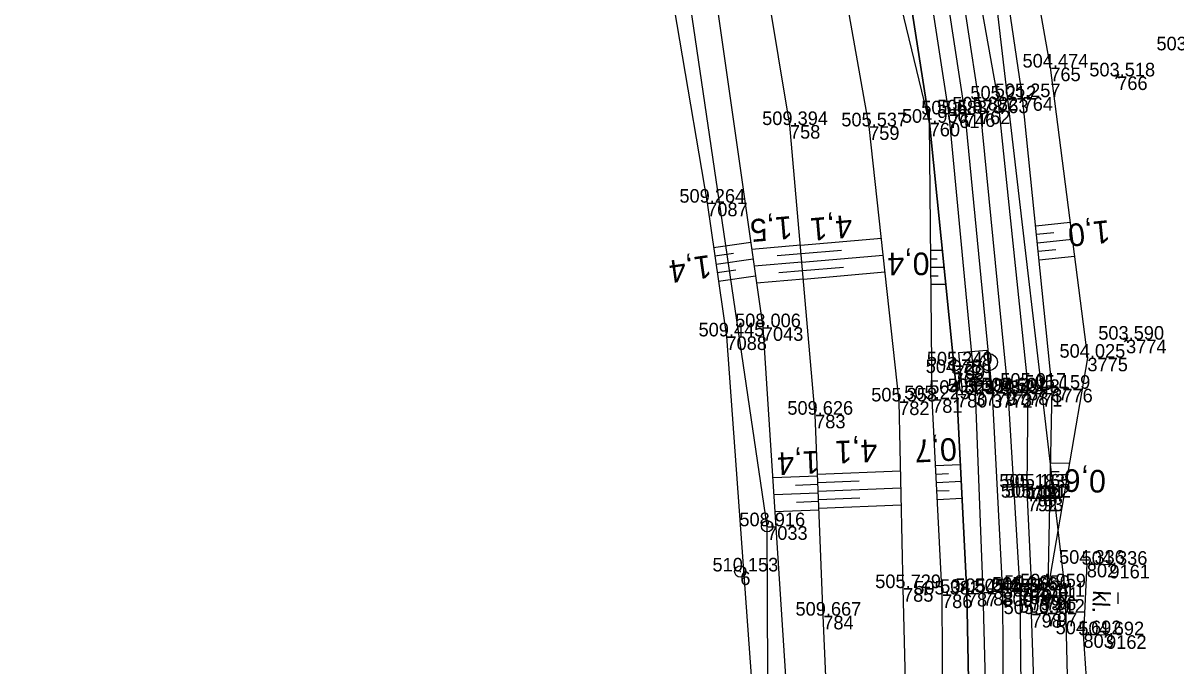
# Model space of a CAD drawing. Extents: x -1234191 to 23050, y -1290331 to -741191.
# Drawn here: x -865217.8 to -865116.1, y -1106225.5 to -1106168.8 of the extents above; entities that cross this region are included whole.
import ezdxf

# ---------------------------------------------------------------- set-up
doc = ezdxf.new("R2010")
doc.units = 0
for name, color, linetype in [('Vrstva 1', 7, 'Continuous'), ('Vrstva 12', 7, 'Continuous'), ('Vrstva 17', 7, 'Continuous'), ('Vrstva 23', 7, 'Continuous'), ('Vrstva 4', 7, 'Continuous'), ('Vrstva 48', 7, 'Continuous'), ('Vrstva 49', 7, 'Continuous'), ('Vrstva 53', 7, 'Continuous'), ('Vrstva 59', 7, 'Continuous'), ('Vrstva 60', 7, 'Continuous'), ('Vrstva 61', 7, 'Continuous'), ('Vrstva 7', 7, 'Continuous')]:
    doc.layers.add(name, color=color, linetype=linetype)

msp = doc.modelspace()

# ---------------------------------------------------------------- linework, layer by layer
at = {"layer": 'Vrstva 1'}
msp.add_lwpolyline([(-865174.08, -1106040), (-865166.92, -1106056.41), (-865158.01, -1106079.46), (-865150.22, -1106103.28), (-865143.69, -1106127.44), (-865138.53, -1106151.75), (-865134.7, -1106176.74), (-865132.31, -1106201.52), (-865131.4, -1106219.01), (-865131.3, -1106235.96), (-865131.5, -1106253.76), (-865132.36, -1106271.32), (-865133.64, -1106288.75), (-865135.22, -1106305.91), (-865138.2, -1106334.81), (-865141.69, -1106364.63), (-865143.95, -1106381.71)], dxfattribs=at)
at = {"layer": 'Vrstva 12'}
for points in [[(-865129.18, -1106210.65), (-865128.71, -1106210.64), (-865128.76, -1106209.76), (-865129.22, -1106209.77), (-865129.18, -1106210.65)], [(-865128.92, -1106219.38), (-865128.83, -1106220.92), (-865127.48, -1106220.8), (-865127.56, -1106219.39), (-865128.92, -1106219.38)]]:
    msp.add_lwpolyline(points, dxfattribs=at)
at = {"layer": 'Vrstva 17'}
msp.add_lwpolyline([(-865116.63, -1106239.62), (-865123.11, -1106239.52), (-865124.25, -1106222.7)], dxfattribs=at)
at = {"layer": 'Vrstva 23'}
for p, q in [((-865123.95, -1106216.48), (-865124.25, -1106222.7)), ((-865121.96, -1106216.57), (-865123.95, -1106216.48)), ((-865122.25, -1106222.79), (-865124.25, -1106222.7))]:
    msp.add_line(p, q, dxfattribs=at)
at = {"layer": 'Vrstva 4'}
for points in [[(-865236.51, -1105919.7), (-865214.37, -1105959.25), (-865205.71, -1105975.1), (-865197.04, -1105990.91), (-865188.45, -1106007.02), (-865180.58, -1106022.78), (-865172.44, -1106039.34), (-865165.47, -1106055.61), (-865156.6, -1106078.95), (-865148.77, -1106102.82), (-865142.37, -1106126.99), (-865137.15, -1106151.58), (-865133.37, -1106176.49), (-865130.91, -1106201.27), (-865129.85, -1106218.85), (-865129.68, -1106236.02), (-865129.85, -1106253.8), (-865130.86, -1106271.38), (-865132.17, -1106288.96), (-865133.64, -1106306.37), (-865136.71, -1106335.02), (-865140.22, -1106364.77), (-865141.26, -1106380.09)], [(-865141.7, -1106384.02), (-865141.48, -1106382.1), (-865141.26, -1106380.09), (-865140.93, -1106380.13), (-865137.57, -1106365.54), (-865134.22, -1106335.14), (-865132.24, -1106305.72), (-865130.43, -1106288.93), (-865129.37, -1106271.69), (-865128.1, -1106253.65), (-865128.27, -1106236.91), (-865128.83, -1106220.92), (-865128.92, -1106219.38), (-865128.79, -1106218.7), (-865129.18, -1106210.65), (-865129.22, -1106209.77), (-865129.13, -1106200.86), (-865131.77, -1106175.52), (-865136.09, -1106151.35), (-865140.57, -1106126.71), (-865146.91, -1106102.51), (-865155.58, -1106078.5), (-865164.28, -1106054.67), (-865171.3, -1106038.77)], [(-865145.89, -1106379.61), (-865143.24, -1106364.36), (-865139.63, -1106334.83), (-865136.46, -1106306.14), (-865135.09, -1106288.85), (-865133.93, -1106271.25), (-865133.16, -1106253.59), (-865132.64, -1106235.93), (-865133.1, -1106218.97), (-865133.77, -1106201.34), (-865136.1, -1106176.83), (-865139.91, -1106152.03), (-865145.18, -1106127.74), (-865151.7, -1106103.58), (-865159.15, -1106079.93), (-865168.18, -1106056.94), (-865175.38, -1106040.63)], [(-865177.51, -1106041.45), (-865169.99, -1106057.67), (-865161.37, -1106080.59), (-865153.44, -1106104.36), (-865147.17, -1106128.33), (-865141.76, -1106152.31), (-865137.81, -1106177.57), (-865135.4, -1106201.49), (-865134.53, -1106219.05), (-865134.22, -1106235.97), (-865134.6, -1106253.74), (-865135.58, -1106271.32), (-865136.69, -1106288.77), (-865137.94, -1106305.84), (-865141.07, -1106334.59), (-865145.11, -1106363.9), (-865146.3, -1106379.55), (-865145.89, -1106379.61)]]:
    msp.add_lwpolyline(points, dxfattribs=at)
at = {"layer": 'Vrstva 48'}
for p, q in [((-865128.46, -1106186.66), (-865125.43, -1106186.35)), ((-865128.39, -1106187.41), (-865126.86, -1106187.25)), ((-865156.86, -1106188.57), (-865153.59, -1106188.1)), ((-865149.21, -1106188.37), (-865153.5, -1106188.75)), ((-865149.21, -1106188.37), (-865142.07, -1106187.75)), ((-865128.31, -1106188.15), (-865125.24, -1106187.84)), ((-865156.75, -1106189.31), (-865155.12, -1106189.07)), ((-865149.14, -1106189.12), (-865151.27, -1106189.31)), ((-865149.14, -1106189.11), (-865145.57, -1106188.8)), ((-865149.08, -1106189.86), (-865141.91, -1106189.24)), ((-865137.71, -1106188.82), (-865136.68, -1106188.81)), ((-865128.23, -1106188.9), (-865126.69, -1106188.74)), ((-865128.16, -1106189.65), (-865125.05, -1106189.33)), ((-865156.65, -1106190.05), (-865153.38, -1106189.58)), ((-865149.08, -1106189.87), (-865153.29, -1106190.23)), ((-865149.02, -1106190.61), (-865145.42, -1106190.3)), ((-865137.7, -1106189.57), (-865137.15, -1106189.57)), ((-865137.7, -1106190.32), (-865136.53, -1106190.31)), ((-865156.54, -1106190.79), (-865154.91, -1106190.56)), ((-865156.43, -1106191.54), (-865153.17, -1106191.07)), ((-865148.95, -1106191.36), (-865153.07, -1106191.72)), ((-865149.01, -1106190.62), (-865151.1, -1106190.8)), ((-865148.95, -1106191.36), (-865141.75, -1106190.73)), ((-865137.69, -1106191.07), (-865137.07, -1106191.07)), ((-865137.68, -1106191.82), (-865136.37, -1106191.81)), ((-865137.3, -1106207.82), (-865135.09, -1106207.71)), ((-865127.14, -1106207.58), (-865125.5, -1106207.61)), ((-865147.69, -1106208.75), (-865151.65, -1106208.91)), ((-865147.7, -1106208.57), (-865140.38, -1106208.27)), ((-865137.26, -1106208.57), (-865136.15, -1106208.51)), ((-865127.16, -1106208.33), (-865126.39, -1106208.34)), ((-865147.66, -1106209.5), (-865149.63, -1106209.58)), ((-865147.67, -1106209.32), (-865144.02, -1106209.17)), ((-865147.64, -1106210.07), (-865140.34, -1106209.77)), ((-865137.22, -1106209.32), (-865135.01, -1106209.2)), ((-865127.19, -1106209.83), (-865126.54, -1106209.84)), ((-865127.17, -1106209.08), (-865125.75, -1106209.11)), ((-865147.63, -1106210.25), (-865151.56, -1106210.41)), ((-865147.61, -1106210.82), (-865143.97, -1106210.67)), ((-865137.18, -1106210.06), (-865136.08, -1106210.01)), ((-865137.14, -1106210.81), (-865134.94, -1106210.7)), ((-865127.2, -1106210.58), (-865126.01, -1106210.6)), ((-865147.57, -1106211.75), (-865151.46, -1106211.91)), ((-865147.6, -1106211), (-865149.55, -1106211.08)), ((-865147.58, -1106211.57), (-865140.31, -1106211.27))]:
    msp.add_line(p, q, dxfattribs=at)
at = {"layer": 'Vrstva 49'}
for p, q in [((-865121.48, -1106173.33), (-865121.07, -1106173.62)), ((-865121.13, -1106173.27), (-865121.42, -1106173.68)), ((-865120.68, -1106196.55), (-865120.29, -1106196.87)), ((-865120.33, -1106196.52), (-865120.65, -1106196.91))]:
    msp.add_line(p, q, dxfattribs=at)
for points in [[(-865248.48, -1105938.27), (-865237.75, -1105960.32), (-865219, -1105992.85), (-865195.39, -1106038.71), (-865183.02, -1106068.8), (-865169.19, -1106106.68), (-865159.48, -1106146.73), (-865152.52, -1106195.61), (-865150.4, -1106228.21), (-865150, -1106273.86), (-865151.77, -1106298.15), (-865154.53, -1106323.47), (-865155.1, -1106347.33), (-865155.48, -1106356.04)], [(-865145.94, -1106363.57), (-865142.64, -1106334.62), (-865139.29, -1106305.46), (-865137.62, -1106288.58), (-865139.33, -1106271.91), (-865139.98, -1106253.67), (-865139.71, -1106236.34), (-865140.16, -1106218.63), (-865140.5, -1106202.16), (-865143.15, -1106177.89), (-865147.63, -1106152.54), (-865151.89, -1106128.68), (-865158.01, -1106106.65), (-865166.09, -1106083.22), (-865174.81, -1106060.27), (-865182.22, -1106042.37), (-865189.98, -1106028.2), (-865197.42, -1106013), (-865203.01, -1106003.11), (-865213.2, -1105984.62), (-865220.4, -1105970.94), (-865239.79, -1105937.65)], [(-865155.48, -1106356.04), (-865151.68, -1106354.48), (-865149.3, -1106324.02), (-865147.43, -1106302.26), (-865147.23, -1106283.88), (-865146.7, -1106266.35), (-865146.43, -1106254.76), (-865146.52, -1106236.51), (-865147.19, -1106221.06), (-865147.91, -1106203.33), (-865150.13, -1106177.77), (-865154.11, -1106153.82), (-865158.52, -1106132.86), (-865164.63, -1106109.25), (-865174.13, -1106081.15), (-865182.3, -1106061.24), (-865188.6, -1106046.2), (-865195.38, -1106031.76), (-865203.75, -1106015.41), (-865210.88, -1106001.89), (-865218.69, -1105987.34), (-865233.44, -1105960.2), (-865244.5, -1105938.75)], [(-865127.37, -1106218.56), (-865127, -1106201.04), (-865129.61, -1106175.31), (-865133.23, -1106150.78), (-865138.55, -1106126.31), (-865140.86, -1106117.48), (-865147.92, -1106094.71), (-865153.79, -1106077.74), (-865163.01, -1106054.44), (-865168.93, -1106038.44), (-865178.61, -1106020.85), (-865186.96, -1106006.27), (-865196.36, -1105989.49), (-865203.41, -1105973.74), (-865210.89, -1105957.77), (-865216, -1105940.86)], [(-865216, -1105940.86), (-865209.6, -1105955.15), (-865202.33, -1105969.04), (-865194.33, -1105988.74), (-865185.26, -1106005.63), (-865177.36, -1106020.26), (-865168.93, -1106038.44), (-865158.94, -1106054.9), (-865150.77, -1106078.05), (-865143.25, -1106101.54), (-865134.36, -1106126.45), (-865131.26, -1106149.56), (-865127.17, -1106172.7), (-865123.9, -1106198.3), (-865127.37, -1106218.56)], [(-865172.84, -1106108.85), (-865164.75, -1106141.56), (-865157.43, -1106184.62), (-865155.73, -1106196.42), (-865153.26, -1106230.42), (-865153.12, -1106269.97), (-865155.13, -1106299.71), (-865157.12, -1106321.56), (-865157.7, -1106345.27), (-865155.48, -1106356.04)], [(-865137.81, -1106177.57), (-865143.88, -1106152.53), (-865147.17, -1106128.33)], [(-865137.62, -1106288.58), (-865135.58, -1106271.32), (-865134.6, -1106253.74), (-865134.22, -1106235.97), (-865134.53, -1106219.05), (-865135.4, -1106201.49), (-865137.81, -1106177.57), (-865141.76, -1106152.31), (-865147.17, -1106128.33)], [(-865137.62, -1106288.58), (-865137.14, -1106271.82), (-865136.6, -1106253.76), (-865136.63, -1106236.13), (-865136.72, -1106219.19), (-865137.59, -1106201.96), (-865137.81, -1106177.57)]]:
    msp.add_lwpolyline(points, dxfattribs=at)
at = {"layer": 'Vrstva 53'}
for p, q in [((-865152.14, -1106213.12), (-865152.14, -1106213.22)), ((-865154.56, -1106217.16), (-865154.46, -1106217.16))]:
    msp.add_line(p, q, dxfattribs=at)
for points in [[(-865227.66, -1105917.88), (-865232.36, -1105922.35), (-865183.09, -1106010.41), (-865167.99, -1106045.38), (-865144.78, -1106101.17), (-865131.99, -1106166.39), (-865125.85, -1106219.01), (-865125.39, -1106238.65), (-865125.96, -1106278.9), (-865132.87, -1106334.65), (-865136.85, -1106381.38), (-865151.63, -1106445.1), (-865163.44, -1106490.83), (-865178.82, -1106535.04), (-865200.93, -1106584.09), (-865238.82, -1106657.44), (-865256.95, -1106698.52)], [(-865292.28, -1106759.44), (-865281, -1106690.92), (-865292.09, -1106688.29), (-865256.12, -1106617.24), (-865192.39, -1106497.22), (-865182.07, -1106466.18), (-865172.59, -1106441.08), (-865160.97, -1106443.62), (-865159.33, -1106435.02), (-865146.44, -1106359.55), (-865157.51, -1106356.95), (-865157, -1106331.91), (-865151.9, -1106265.92), (-865152.14, -1106213.17), (-865160.59, -1106155.82), (-865173.12, -1106100.65), (-865192.84, -1106055.27), (-865212.4, -1106009.43), (-865251.57, -1105941.08), (-865241.97, -1105927.13)]]:
    msp.add_lwpolyline(points, dxfattribs=at)
for centre in [(-865152.14, -1106213.17), (-865154.51, -1106217.16)]:
    msp.add_circle(centre, 0.499, dxfattribs=at)
at = {"layer": 'Vrstva 59'}
msp.add_line((-865121.19, -1106220.02), (-865121.2, -1106219.02), dxfattribs=at)
at = {"layer": 'Vrstva 60'}
for p, q in [((-865127.17, -1106172.7), (-865127.17, -1106172.7)), ((-865121.27, -1106173.48), (-865121.27, -1106173.48)), ((-865131.77, -1106175.52), (-865131.77, -1106175.52)), ((-865129.61, -1106175.31), (-865129.61, -1106175.31)), ((-865136.1, -1106176.83), (-865136.1, -1106176.83)), ((-865134.7, -1106176.74), (-865134.7, -1106176.74)), ((-865133.37, -1106176.49), (-865133.37, -1106176.49)), ((-865150.13, -1106177.77), (-865150.13, -1106177.77)), ((-865143.15, -1106177.89), (-865143.15, -1106177.89)), ((-865137.81, -1106177.57), (-865137.81, -1106177.57)), ((-865157.43, -1106184.62), (-865157.43, -1106184.62)), ((-865155.73, -1106196.42), (-865155.73, -1106196.42)), ((-865152.52, -1106195.61), (-865152.52, -1106195.61)), ((-865120.49, -1106196.71), (-865120.49, -1106196.71)), ((-865123.9, -1106198.3), (-865123.9, -1106198.3)), ((-865135.71, -1106199.65), (-865135.71, -1106199.65)), ((-865135.61, -1106198.98), (-865135.61, -1106198.98)), ((-865135.4, -1106201.49), (-865135.4, -1106201.49)), ((-865133.77, -1106201.34), (-865133.77, -1106201.34)), ((-865132.31, -1106201.52), (-865132.31, -1106201.52)), ((-865130.91, -1106201.27), (-865130.91, -1106201.27)), ((-865129.68, -1106201.41), (-865129.68, -1106201.41)), ((-865129.13, -1106200.86), (-865129.13, -1106200.86)), ((-865127, -1106201.04), (-865127, -1106201.04)), ((-865140.5, -1106202.16), (-865140.5, -1106202.16)), ((-865137.59, -1106201.96), (-865137.59, -1106201.96)), ((-865147.91, -1106203.33), (-865147.91, -1106203.33)), ((-865129.22, -1106209.77), (-865129.22, -1106209.77)), ((-865128.76, -1106209.76), (-865128.76, -1106209.76)), ((-865129.18, -1106210.65), (-865129.18, -1106210.65)), ((-865128.71, -1106210.64), (-865128.71, -1106210.64)), ((-865152.14, -1106213.17), (-865152.14, -1106213.17)), ((-865123.95, -1106216.48), (-865123.95, -1106216.48)), ((-865121.96, -1106216.57), (-865121.96, -1106216.57)), ((-865154.51, -1106217.16), (-865154.51, -1106217.16)), ((-865140.16, -1106218.63), (-865140.16, -1106218.63)), ((-865133.1, -1106218.97), (-865133.1, -1106218.97)), ((-865129.85, -1106218.85), (-865129.85, -1106218.85)), ((-865128.79, -1106218.7), (-865128.79, -1106218.7)), ((-865127.37, -1106218.56), (-865127.37, -1106218.56)), ((-865136.72, -1106219.19), (-865136.72, -1106219.19)), ((-865134.53, -1106219.05), (-865134.53, -1106219.05)), ((-865131.4, -1106219.01), (-865131.4, -1106219.01)), ((-865128.92, -1106219.38), (-865128.92, -1106219.38)), ((-865127.56, -1106219.39), (-865127.56, -1106219.39)), ((-865128.83, -1106220.92), (-865128.83, -1106220.92)), ((-865127.48, -1106220.8), (-865127.48, -1106220.8)), ((-865147.19, -1106221.06), (-865147.19, -1106221.06)), ((-865124.25, -1106222.7), (-865124.25, -1106222.7)), ((-865122.25, -1106222.79), (-865122.25, -1106222.79))]:
    msp.add_line(p, q, dxfattribs=at)
at = {"layer": 'Vrstva 7'}
for p, q in [((-865135.71, -1106199.65), (-865135.09, -1106199.59)), ((-865135.61, -1106198.93), (-865135.6, -1106199.03)), ((-865129.18, -1106201.38), (-865130.18, -1106201.44)), ((-865129.7, -1106200.91), (-865129.65, -1106201.91))]:
    msp.add_line(p, q, dxfattribs=at)
msp.add_lwpolyline([(-865135.25, -1106197.85), (-865132.78, -1106197.62), (-865132.45, -1106201.09), (-865134.92, -1106201.33)], close=True, dxfattribs=at)
for centre, radius in [((-865135.61, -1106198.98), 0.5), ((-865132.59, -1106198.69), 0.75)]:
    msp.add_circle(centre, radius, dxfattribs=at)

# ---------------------------------------------------------------- texts
at = {"layer": 'Vrstva 23'}
msp.add_text('kl.', height=1.5, rotation=267.2838, dxfattribs=at).set_placement((-865123.39, -1106218.81))
at = {"layer": 'Vrstva 48'}
for s, rotation, p in [('1,5', 184.9533, (-865150.01, -1106185.79)), ('4,1', 184.9533, (-865144.71, -1106185.68)), ('1,0', 185.8067, (-865122, -1106186.15)), ('1,4', 188.1777, (-865157.22, -1106189.22)), ('0,4', 180.5168, (-865137.83, -1106189.01)), ('4,1', 182.3222, (-865142.46, -1106205.5)), ('0,7', 182.8976, (-865135.47, -1106205.37)), ('1,4', 182.3222, (-865147.56, -1106206.51)), ('0,6', 178.7772, (-865122.25, -1106208.21))]:
    msp.add_text(s, height=2, rotation=rotation, dxfattribs=at).set_placement(p)
at = {"layer": 'Vrstva 60'}
for s, p in [('765', (-865127.17, -1106173.9)), ('766', (-865121.27, -1106174.68)), ('763', (-865131.77, -1106176.72)), ('764', (-865129.61, -1106176.51)), ('761', (-865136.1, -1106178.03)), ('746', (-865134.7, -1106177.94)), ('762', (-865133.37, -1106177.69)), ('758', (-865150.13, -1106178.97)), ('759', (-865143.15, -1106179.08)), ('760', (-865137.81, -1106178.77)), ('7087', (-865157.43, -1106185.82)), ('7043', (-865152.52, -1106196.81)), ('7088', (-865155.73, -1106197.62)), ('3774', (-865120.49, -1106197.91)), ('3775', (-865123.9, -1106199.5)), ('768', (-865135.71, -1106200.85)), ('769', (-865135.61, -1106200.18)), ('780', (-865135.4, -1106202.69)), ('3779', (-865133.77, -1106202.54)), ('3772', (-865132.31, -1106202.72)), ('3778', (-865130.91, -1106202.47)), ('3771', (-865129.68, -1106202.61)), ('3777', (-865129.13, -1106202.06)), ('3776', (-865127, -1106202.24)), ('782', (-865140.5, -1106203.36)), ('781', (-865137.59, -1106203.16)), ('783', (-865147.91, -1106204.53)), ('795', (-865129.22, -1106210.97)), ('794', (-865128.76, -1106210.96)), ('792', (-865129.18, -1106211.85)), ('793', (-865128.71, -1106211.84)), ('7033', (-865152.14, -1106214.37)), ('802', (-865123.95, -1106217.68)), ('9161', (-865121.96, -1106217.77)), ('6', (-865154.51, -1106218.36)), ('785', (-865140.16, -1106219.83)), ('788', (-865133.1, -1106220.17)), ('789', (-865129.85, -1106220.05)), ('790', (-865128.79, -1106219.9)), ('791', (-865127.37, -1106219.76)), ('786', (-865136.72, -1106220.39)), ('787', (-865134.53, -1106220.25)), ('800', (-865131.4, -1106220.21)), ('799', (-865128.92, -1106220.58)), ('796', (-865127.56, -1106220.59)), ('798', (-865128.83, -1106222.11)), ('797', (-865127.48, -1106222)), ('784', (-865147.19, -1106222.27)), ('803', (-865124.25, -1106223.9)), ('9162', (-865122.25, -1106223.99))]:
    msp.add_text(s, height=1.2, dxfattribs=at).set_placement(p)
at = {"layer": 'Vrstva 61'}
for s, p in [('503.019', (-865117.81, -1106171.18)), ('504.474', (-865129.62, -1106172.7)), ('503.518', (-865123.73, -1106173.48)), ('505.257', (-865132.07, -1106175.31)), ('505.212', (-865134.22, -1106175.52)), ('505.683', (-865138.55, -1106176.83)), ('505.878', (-865137.16, -1106176.74)), ('505.832', (-865135.81, -1106176.49)), ('509.394', (-865152.58, -1106177.77)), ('505.537', (-865145.6, -1106177.89)), ('504.900', (-865140.26, -1106177.57)), ('509.264', (-865159.88, -1106184.62)), ('508.006', (-865154.97, -1106195.61)), ('509.445', (-865158.19, -1106196.42)), ('503.590', (-865122.94, -1106196.71)), ('504.025', (-865126.36, -1106198.3)), ('504.786', (-865138.16, -1106199.65)), ('505.249', (-865138.06, -1106198.98)), ('505.017', (-865131.58, -1106200.86)), ('504.623', (-865137.85, -1106201.49)), ('505.384', (-865136.22, -1106201.34)), ('505.634', (-865134.76, -1106201.52)), ('505.601', (-865133.27, -1106201.27)), ('505.543', (-865132.13, -1106201.41)), ('505.159', (-865129.45, -1106201.04)), ('505.358', (-865142.96, -1106202.16)), ('505.225', (-865140.05, -1106201.96)), ('509.626', (-865150.36, -1106203.33)), ('505.183', (-865131.67, -1106209.77)), ('505.165', (-865131.21, -1106209.76)), ('505.191', (-865131.54, -1106210.65)), ('505.152', (-865131.16, -1106210.64)), ('508.916', (-865154.59, -1106213.17)), ('504.336', (-865126.4, -1106216.48)), ('504.336', (-865124.41, -1106216.57)), ('510.153', (-865156.96, -1106217.16)), ('505.729', (-865142.61, -1106218.63)), ('505.382', (-865139.17, -1106219.19)), ('504.541', (-865136.88, -1106219.05)), ('505.242', (-865135.55, -1106218.97)), ('505.455', (-865133.85, -1106219.01)), ('505.366', (-865132.31, -1106218.85)), ('504.950', (-865131.24, -1106218.7)), ('504.959', (-865129.83, -1106218.56)), ('505.134', (-865131.37, -1106219.38)), ('505.111', (-865129.92, -1106219.39)), ('509.667', (-865149.64, -1106221.06)), ('505.039', (-865131.29, -1106220.92)), ('505.112', (-865129.93, -1106220.8)), ('504.692', (-865126.7, -1106222.7)), ('504.692', (-865124.7, -1106222.79))]:
    msp.add_text(s, height=1.2, dxfattribs=at).set_placement(p)
at = {"layer": 'Vrstva 7'}
msp.add_text('KM', height=1.247, rotation=275.5068, dxfattribs=at).set_placement((-865134.57, -1106198.52))

doc.saveas('drawing.dxf')
